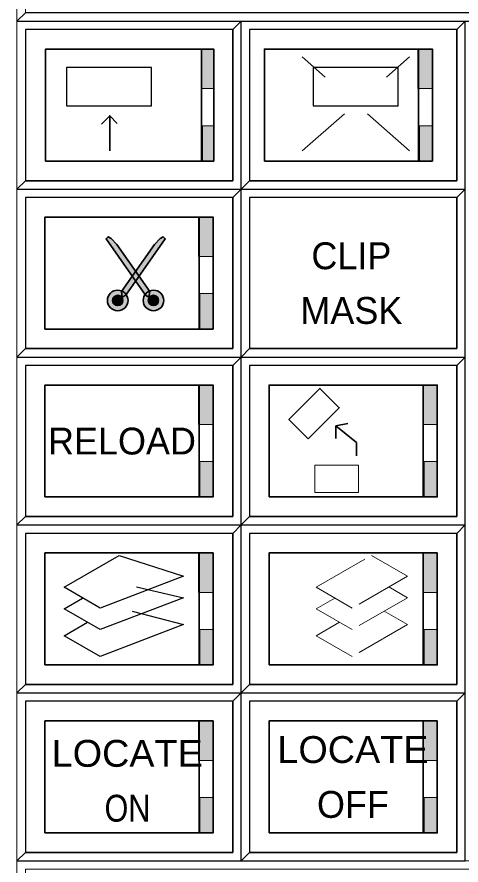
# Model space of a CAD drawing. Extents: x 95906.8 to 95923.6, y 90964.8 to 90972.8.
# Drawn here: x 95916.332 to 95917.125, y 90966.454 to 90967.969 of the extents above; entities that cross this region are included whole.
import ezdxf
from ezdxf.enums import TextEntityAlignment as Align

# ---------------------------------------------------------------- set-up
doc = ezdxf.new("R2010")
doc.units = 0
doc.header["$LTSCALE"] = 0.019
doc.linetypes.add('MEDIUM_DASHED', pattern=[4.5, 3, -1.5])
for name, color, linetype, lineweight in [('11', 7, 'Continuous', 25), ('12', 7, 'Continuous', 25), ('2', 7, 'Continuous', 13), ('3', 7, 'Continuous', 25), ('6', 7, 'Continuous', 25)]:
    doc.layers.add(name, color=color, linetype=linetype, lineweight=lineweight)

msp = doc.modelspace()

# ---------------------------------------------------------------- hatches: boundary and pattern name
at = {"layer": '6'}
for points in [[(95916.6835, 90967.9117), (95916.6608, 90967.9117), (95916.6608, 90967.8412), (95916.6835, 90967.8412)], [(95917.0738, 90967.9117), (95917.048, 90967.9117), (95917.048, 90967.8412), (95917.0738, 90967.8412)], [(95916.6632, 90967.7117), (95916.6835, 90967.7117), (95916.6835, 90967.775), (95916.6632, 90967.775)], [(95917.0504, 90967.7117), (95917.0738, 90967.7117), (95917.0738, 90967.775), (95917.0504, 90967.775)], [(95916.6823, 90967.6117), (95916.6565, 90967.6117), (95916.6565, 90967.5412), (95916.6823, 90967.5412)], [(95916.5617, 90967.4723), (95916.4912, 90967.573), (95916.4949, 90967.5765), (95916.5003, 90967.5732), (95916.5105, 90967.563), (95916.5694, 90967.4788), (95916.5677, 90967.4688)], [(95916.5263, 90967.4723), (95916.5968, 90967.573), (95916.5931, 90967.5765), (95916.5877, 90967.5732), (95916.5775, 90967.563), (95916.5186, 90967.4788), (95916.5203, 90967.4688)], [(95916.5305, 90967.4628, 1), (95916.4937, 90967.4628, 1)], [(95916.5575, 90967.4628, 1), (95916.5943, 90967.4628, 1)], [(95916.5213, 90967.4628, 1), (95916.5029, 90967.4628, 1)], [(95916.5667, 90967.4628, 1), (95916.5851, 90967.4628, 1)], [(95916.6589, 90967.4117), (95916.6823, 90967.4117), (95916.6823, 90967.475), (95916.6589, 90967.475)], [(95916.6823, 90967.3117), (95916.6565, 90967.3117), (95916.6565, 90967.2412), (95916.6823, 90967.2412)], [(95917.0823, 90967.3117), (95917.0565, 90967.3117), (95917.0565, 90967.2412), (95917.0823, 90967.2412)], [(95916.6589, 90967.1117), (95916.6823, 90967.1117), (95916.6823, 90967.175), (95916.6589, 90967.175)], [(95917.0589, 90967.1117), (95917.0823, 90967.1117), (95917.0823, 90967.175), (95917.0589, 90967.175)], [(95916.6823, 90967.0117), (95916.6565, 90967.0117), (95916.6565, 90966.9412), (95916.6823, 90966.9412)], [(95917.0823, 90967.0117), (95917.0565, 90967.0117), (95917.0565, 90966.9412), (95917.0823, 90966.9412)], [(95916.6589, 90966.8117), (95916.6823, 90966.8117), (95916.6823, 90966.875), (95916.6589, 90966.875)], [(95917.0589, 90966.8117), (95917.0823, 90966.8117), (95917.0823, 90966.875), (95917.0589, 90966.875)], [(95916.6823, 90966.7117), (95916.6565, 90966.7117), (95916.6565, 90966.6412), (95916.6823, 90966.6412)], [(95917.0823, 90966.7117), (95917.0565, 90966.7117), (95917.0565, 90966.6412), (95917.0823, 90966.6412)], [(95916.6589, 90966.5117), (95916.6823, 90966.5117), (95916.6823, 90966.575), (95916.6589, 90966.575)], [(95917.0589, 90966.5117), (95917.0823, 90966.5117), (95917.0823, 90966.575), (95917.0589, 90966.575)]]:
    msp.add_hatch(color=256, dxfattribs=at).paths.add_polyline_path(points)

# ---------------------------------------------------------------- linework, layer by layer
at = {"layer": '11'}
for points in [[(95916.7473, 90967.6767), (95917.1173, 90967.6767), (95917.1173, 90967.9467), (95916.7473, 90967.9467)], [(95916.3473, 90967.3767), (95916.7173, 90967.3767), (95916.7173, 90967.6467), (95916.3473, 90967.6467)], [(95916.7473, 90967.3767), (95917.1173, 90967.3767), (95917.1173, 90967.6467), (95916.7473, 90967.6467)], [(95916.3473, 90967.0767), (95916.7173, 90967.0767), (95916.7173, 90967.3467), (95916.3473, 90967.3467)], [(95916.7473, 90967.0767), (95917.1173, 90967.0767), (95917.1173, 90967.3467), (95916.7473, 90967.3467)], [(95916.3473, 90966.7767), (95916.7173, 90966.7767), (95916.7173, 90967.0467), (95916.3473, 90967.0467)], [(95916.7473, 90966.7767), (95917.1173, 90966.7767), (95917.1173, 90967.0467), (95916.7473, 90967.0467)], [(95916.3473, 90966.4767), (95916.7173, 90966.4767), (95916.7173, 90966.7467), (95916.3473, 90966.7467)], [(95916.7473, 90966.4767), (95917.1173, 90966.4767), (95917.1173, 90966.7467), (95916.7473, 90966.7467)]]:
    msp.add_lwpolyline(points, close=True, dxfattribs=at)
at = {"layer": '12'}
msp.add_lwpolyline([(95916.3473, 90967.6767), (95916.7173, 90967.6767), (95916.7173, 90967.9467), (95916.3473, 90967.9467)], close=True, dxfattribs=at)
at = {"layer": '2'}
for points in [[(95916.3323, 90968.0617), (95916.3323, 90967.9617), (95916.3473, 90967.9767), (95916.3473, 90968.0467), (95917.9173, 90968.0467), (95917.9323, 90968.0617)], [(95916.3323, 90967.9617), (95916.3323, 90967.6617), (95916.3473, 90967.6767), (95916.3473, 90967.9467), (95916.7173, 90967.9467), (95916.7323, 90967.9617)], [(95916.7323, 90967.9617), (95916.7323, 90967.6617), (95916.7473, 90967.6767), (95916.7473, 90967.9467), (95917.1173, 90967.9467), (95917.1323, 90967.9617)], [(95916.3323, 90967.6617), (95916.3323, 90967.3617), (95916.3473, 90967.3767), (95916.3473, 90967.6467), (95916.7173, 90967.6467), (95916.7323, 90967.6617)], [(95916.7323, 90967.6617), (95916.7323, 90967.3617), (95916.7473, 90967.3767), (95916.7473, 90967.6467), (95917.1173, 90967.6467), (95917.1323, 90967.6617)], [(95916.3323, 90967.3617), (95916.3323, 90967.0617), (95916.3473, 90967.0767), (95916.3473, 90967.3467), (95916.7173, 90967.3467), (95916.7323, 90967.3617)], [(95916.7323, 90967.3617), (95916.7323, 90967.0617), (95916.7473, 90967.0767), (95916.7473, 90967.3467), (95917.1173, 90967.3467), (95917.1323, 90967.3617)], [(95916.3323, 90967.0617), (95916.3323, 90966.7617), (95916.3473, 90966.7767), (95916.3473, 90967.0467), (95916.7173, 90967.0467), (95916.7323, 90967.0617)], [(95916.7323, 90967.0617), (95916.7323, 90966.7617), (95916.7473, 90966.7767), (95916.7473, 90967.0467), (95917.1173, 90967.0467), (95917.1323, 90967.0617)], [(95916.3323, 90966.7617), (95916.3323, 90966.4617), (95916.3473, 90966.4767), (95916.3473, 90966.7467), (95916.7173, 90966.7467), (95916.7323, 90966.7617)], [(95916.7323, 90966.7617), (95916.7323, 90966.4617), (95916.7473, 90966.4767), (95916.7473, 90966.7467), (95917.1173, 90966.7467), (95917.1323, 90966.7617)], [(95916.3323, 90966.4617), (95916.3323, 90966.3617), (95916.3473, 90966.3767), (95916.3473, 90966.4467), (95917.9173, 90966.4467), (95917.9323, 90966.4617)]]:
    msp.add_lwpolyline(points, close=True, dxfattribs=at)
at = {"layer": '3'}
for points in [[(95916.3323, 90967.9617), (95917.9323, 90967.9617), (95917.9323, 90968.0617), (95917.9173, 90968.0467), (95917.9173, 90967.9767), (95916.3473, 90967.9767)], [(95916.3323, 90967.6617), (95916.7323, 90967.6617), (95916.7323, 90967.9617), (95916.7173, 90967.9467), (95916.7173, 90967.6767), (95916.3473, 90967.6767)], [(95916.7323, 90967.6617), (95917.1323, 90967.6617), (95917.1323, 90967.9617), (95917.1173, 90967.9467), (95917.1173, 90967.6767), (95916.7473, 90967.6767)], [(95916.3323, 90967.3617), (95916.7323, 90967.3617), (95916.7323, 90967.6617), (95916.7173, 90967.6467), (95916.7173, 90967.3767), (95916.3473, 90967.3767)], [(95916.7323, 90967.3617), (95917.1323, 90967.3617), (95917.1323, 90967.6617), (95917.1173, 90967.6467), (95917.1173, 90967.3767), (95916.7473, 90967.3767)], [(95916.3323, 90967.0617), (95916.7323, 90967.0617), (95916.7323, 90967.3617), (95916.7173, 90967.3467), (95916.7173, 90967.0767), (95916.3473, 90967.0767)], [(95916.7323, 90967.0617), (95917.1323, 90967.0617), (95917.1323, 90967.3617), (95917.1173, 90967.3467), (95917.1173, 90967.0767), (95916.7473, 90967.0767)], [(95916.3323, 90966.7617), (95916.7323, 90966.7617), (95916.7323, 90967.0617), (95916.7173, 90967.0467), (95916.7173, 90966.7767), (95916.3473, 90966.7767)], [(95916.7323, 90966.7617), (95917.1323, 90966.7617), (95917.1323, 90967.0617), (95917.1173, 90967.0467), (95917.1173, 90966.7767), (95916.7473, 90966.7767)], [(95916.3323, 90966.4617), (95916.7323, 90966.4617), (95916.7323, 90966.7617), (95916.7173, 90966.7467), (95916.7173, 90966.4767), (95916.3473, 90966.4767)], [(95916.7323, 90966.4617), (95917.1323, 90966.4617), (95917.1323, 90966.7617), (95917.1173, 90966.7467), (95917.1173, 90966.4767), (95916.7473, 90966.4767)]]:
    msp.add_lwpolyline(points, close=True, dxfattribs=at)
at = {"layer": '6', "linetype": 'MEDIUM_DASHED', "lineweight": 13}
for p, q in [((95916.8414, 90967.73), (95917.033, 90967.8979)), ((95917.033, 90967.73), (95916.8414, 90967.8979))]:
    msp.add_line(p, q, dxfattribs=at)
at = {"layer": '6', "lineweight": 35}
for p, q in [((95916.4978, 90967.7927), (95916.483, 90967.7779)), ((95916.9014, 90967.2385), (95916.9226, 90967.2432))]:
    msp.add_line(p, q, dxfattribs=at)
at = {"layer": '6', "lineweight": 13}
for p, q in [((95916.7173, 90967.403), (95916.7173, 90967.6147)), ((95916.7173, 90967.103), (95916.7173, 90967.3147)), ((95916.7173, 90967.103), (95916.7173, 90967.3147)), ((95916.7173, 90967.103), (95916.7173, 90967.3147)), ((95917.1173, 90966.803), (95917.1173, 90967.0147)), ((95917.1173, 90966.503), (95917.1173, 90966.7147)), ((95917.1173, 90966.503), (95917.1173, 90966.7147))]:
    msp.add_line(p, q, dxfattribs=at)
at = {"layer": '6'}
for p, q in [((95916.7173, 90967.6147), (95916.7173, 90967.403)), ((95916.7173, 90967.3147), (95916.7173, 90967.103)), ((95916.7173, 90967.3147), (95916.7173, 90967.103)), ((95916.7173, 90967.3147), (95916.7173, 90967.103)), ((95917.1173, 90967.0147), (95917.1173, 90966.803)), ((95917.1173, 90966.7147), (95917.1173, 90966.503)), ((95917.1173, 90966.7147), (95917.1173, 90966.503))]:
    msp.add_line(p, q, dxfattribs=at)
at = {"layer": '6', "lineweight": 35}
for points in [[(95916.3835, 90967.7117), (95916.6835, 90967.7117), (95916.6835, 90967.9117), (95916.3835, 90967.9117)], [(95916.6835, 90967.7117), (95916.6616, 90967.7117), (95916.6616, 90967.9117), (95916.6835, 90967.9117)], [(95916.7738, 90967.7117), (95917.0738, 90967.7117), (95917.0738, 90967.9117), (95916.7738, 90967.9117)], [(95917.0738, 90967.7117), (95917.0488, 90967.7117), (95917.0488, 90967.9117), (95917.0738, 90967.9117)], [(95916.3823, 90967.4117), (95916.6823, 90967.4117), (95916.6823, 90967.6117), (95916.3823, 90967.6117)], [(95916.6823, 90967.4117), (95916.6573, 90967.4117), (95916.6573, 90967.6117), (95916.6823, 90967.6117)], [(95916.5617, 90967.4723), (95916.4912, 90967.573), (95916.4949, 90967.5765), (95916.5003, 90967.5732), (95916.5105, 90967.563), (95916.5694, 90967.4788), (95916.5677, 90967.4688)], [(95916.5263, 90967.4723), (95916.5968, 90967.573), (95916.5931, 90967.5765), (95916.5877, 90967.5732), (95916.5775, 90967.563), (95916.5186, 90967.4788), (95916.5203, 90967.4688)], [(95916.3823, 90967.1117), (95916.6823, 90967.1117), (95916.6823, 90967.3117), (95916.3823, 90967.3117)], [(95916.6823, 90967.1117), (95916.6573, 90967.1117), (95916.6573, 90967.3117), (95916.6823, 90967.3117)], [(95916.7823, 90967.1117), (95917.0823, 90967.1117), (95917.0823, 90967.3117), (95916.7823, 90967.3117)], [(95917.0823, 90967.1117), (95917.0573, 90967.1117), (95917.0573, 90967.3117), (95917.0823, 90967.3117)], [(95916.8521, 90967.2157), (95916.9076, 90967.2712), (95916.8731, 90967.3057), (95916.8176, 90967.2502)], [(95916.3823, 90966.8117), (95916.6823, 90966.8117), (95916.6823, 90967.0117), (95916.3823, 90967.0117)], [(95916.6823, 90966.8117), (95916.6573, 90966.8117), (95916.6573, 90967.0117), (95916.6823, 90967.0117)], [(95916.7823, 90966.8117), (95917.0823, 90966.8117), (95917.0823, 90967.0117), (95916.7823, 90967.0117)], [(95917.0823, 90966.8117), (95917.0573, 90966.8117), (95917.0573, 90967.0117), (95917.0823, 90967.0117)], [(95916.3823, 90966.5117), (95916.6823, 90966.5117), (95916.6823, 90966.7117), (95916.3823, 90966.7117)], [(95916.6823, 90966.5117), (95916.6573, 90966.5117), (95916.6573, 90966.7117), (95916.6823, 90966.7117)], [(95916.7823, 90966.5117), (95917.0823, 90966.5117), (95917.0823, 90966.7117), (95916.7823, 90966.7117)], [(95917.0823, 90966.5117), (95917.0573, 90966.5117), (95917.0573, 90966.7117), (95917.0823, 90966.7117)]]:
    msp.add_lwpolyline(points, close=True, dxfattribs=at)
at = {"layer": '6', "lineweight": 13}
for points in [[(95916.6835, 90967.9117), (95916.6608, 90967.9117), (95916.6608, 90967.8412), (95916.6835, 90967.8412)], [(95917.0738, 90967.9117), (95917.048, 90967.9117), (95917.048, 90967.8412), (95917.0738, 90967.8412)], [(95916.6632, 90967.7117), (95916.6835, 90967.7117), (95916.6835, 90967.775), (95916.6632, 90967.775)], [(95917.0504, 90967.7117), (95917.0738, 90967.7117), (95917.0738, 90967.775), (95917.0504, 90967.775)], [(95916.6823, 90967.6117), (95916.6565, 90967.6117), (95916.6565, 90967.5412), (95916.6823, 90967.5412)], [(95916.6589, 90967.4117), (95916.6823, 90967.4117), (95916.6823, 90967.475), (95916.6589, 90967.475)], [(95916.6823, 90967.3117), (95916.6565, 90967.3117), (95916.6565, 90967.2412), (95916.6823, 90967.2412)], [(95917.0823, 90967.3117), (95917.0565, 90967.3117), (95917.0565, 90967.2412), (95917.0823, 90967.2412)], [(95916.6589, 90967.1117), (95916.6823, 90967.1117), (95916.6823, 90967.175), (95916.6589, 90967.175)], [(95917.0589, 90967.1117), (95917.0823, 90967.1117), (95917.0823, 90967.175), (95917.0589, 90967.175)], [(95916.6823, 90967.0117), (95916.6565, 90967.0117), (95916.6565, 90966.9412), (95916.6823, 90966.9412)], [(95917.0823, 90967.0117), (95917.0565, 90967.0117), (95917.0565, 90966.9412), (95917.0823, 90966.9412)], [(95916.6589, 90966.8117), (95916.6823, 90966.8117), (95916.6823, 90966.875), (95916.6589, 90966.875)], [(95917.0589, 90966.8117), (95917.0823, 90966.8117), (95917.0823, 90966.875), (95917.0589, 90966.875)], [(95916.6823, 90966.7117), (95916.6565, 90966.7117), (95916.6565, 90966.6412), (95916.6823, 90966.6412)], [(95917.0823, 90966.7117), (95917.0565, 90966.7117), (95917.0565, 90966.6412), (95917.0823, 90966.6412)], [(95916.6589, 90966.5117), (95916.6823, 90966.5117), (95916.6823, 90966.575), (95916.6589, 90966.575)], [(95917.0589, 90966.5117), (95917.0823, 90966.5117), (95917.0823, 90966.575), (95917.0589, 90966.575)]]:
    msp.add_lwpolyline(points, close=True, dxfattribs=at)
at = {"layer": '6'}
for points in [[(95916.4209, 90967.8104), (95916.5723, 90967.8104), (95916.5723, 90967.879), (95916.4209, 90967.879)], [(95916.8612, 90967.8104), (95917.0126, 90967.8104), (95917.0126, 90967.879), (95916.8612, 90967.879)], [(95916.4163, 90966.9503), (95916.5149, 90967.0073), (95916.6294, 90966.9701), (95916.4807, 90966.9132)]]:
    msp.add_lwpolyline(points, close=True, dxfattribs=at)
at = {"layer": '6', "lineweight": 35}
for points in [[(95916.4978, 90967.73), (95916.4978, 90967.7927), (95916.5114, 90967.7791)], [(95916.938, 90967.1853), (95916.938, 90967.2089), (95916.9014, 90967.2385), (95916.9014, 90967.216)]]:
    msp.add_lwpolyline(points, dxfattribs=at)
at = {"layer": '6', "linetype": 'MEDIUM_DASHED', "lineweight": 13}
for points in [[(95916.8636, 90967.1199), (95916.9421, 90967.1199), (95916.9421, 90967.1687), (95916.8636, 90967.1687)], [(95916.8663, 90966.9503), (95916.9649, 90967.0073), (95917.0294, 90966.9701), (95916.9307, 90966.9132)]]:
    msp.add_lwpolyline(points, close=True, dxfattribs=at)
at = {"layer": '6'}
for points in [[(95916.5458, 90966.9512), (95916.6294, 90966.9318), (95916.4807, 90966.8749), (95916.4163, 90966.9121), (95916.4493, 90966.9311)], [(95916.5376, 90966.9079), (95916.6294, 90966.8837), (95916.4807, 90966.8267), (95916.4163, 90966.8639), (95916.4582, 90966.8879)]]:
    msp.add_lwpolyline(points, dxfattribs=at)
at = {"layer": '6', "linetype": 'MEDIUM_DASHED', "lineweight": 13}
for points in [[(95916.9958, 90966.9512), (95917.0294, 90966.9318), (95916.9307, 90966.8749), (95916.8663, 90966.9121), (95916.8993, 90966.9311)], [(95916.9876, 90966.9079), (95917.0294, 90966.8837), (95916.9307, 90966.8267), (95916.8663, 90966.8639), (95916.9082, 90966.8879)]]:
    msp.add_lwpolyline(points, dxfattribs=at)
at = {"layer": '6', "lineweight": 35}
for centre, radius in [((95916.5121, 90967.4628), 0.0184), ((95916.5759, 90967.4628), 0.0184), ((95916.5121, 90967.4628), 0.00923), ((95916.5759, 90967.4628), 0.00923)]:
    msp.add_circle(centre, radius, dxfattribs=at)

# ---------------------------------------------------------------- texts
at = {"layer": '6'}
for s, p in [('CLIP', (95916.9291, 90967.5186)), ('MASK', (95916.9291, 90967.4209)), ('RELOAD', (95916.5197, 90967.1876)), ('OFF', (95916.9319, 90966.5385))]:
    msp.add_text(s, height=0.048, dxfattribs=at).set_placement(p, align=Align.CENTER)
for s, width, p in [('LOCATE', 1.05, (95916.5291, 90966.6297)), ('LOCATE', 1.05, (95916.9319, 90966.6365)), ('ON', 0.85, (95916.5295, 90966.5317))]:
    msp.add_text(s, height=0.048, dxfattribs=dict(at, width=width)).set_placement(p, align=Align.CENTER)

doc.saveas('drawing.dxf')
